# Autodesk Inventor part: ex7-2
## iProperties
Author: Administrator
Created: 2001-10
Part Number: ex7-2
Document SubType Name: Modeling
Designer: Administrator
Control State: 0
Master: False
Checked Out: False
PropertySet Name: Design Tracking Control
Shininess: 64.0
Angle Display Precision: 2
Document Length Units: 11272
Document Angle Units: 11286
Document Time Units: 11279
Document Mass Units: 11290
Document Length Units Precision: 3
Document Angle Units Precision: 2
Compacted: True
PropertySet Name: _Private Model Information
Density: 0.0
Volumn: 0.0
Area: 0.0
PropertySet Name: Model Information
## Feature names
1. Extrusion1
2. Hole1
3. Hole2
4. Fillet1
